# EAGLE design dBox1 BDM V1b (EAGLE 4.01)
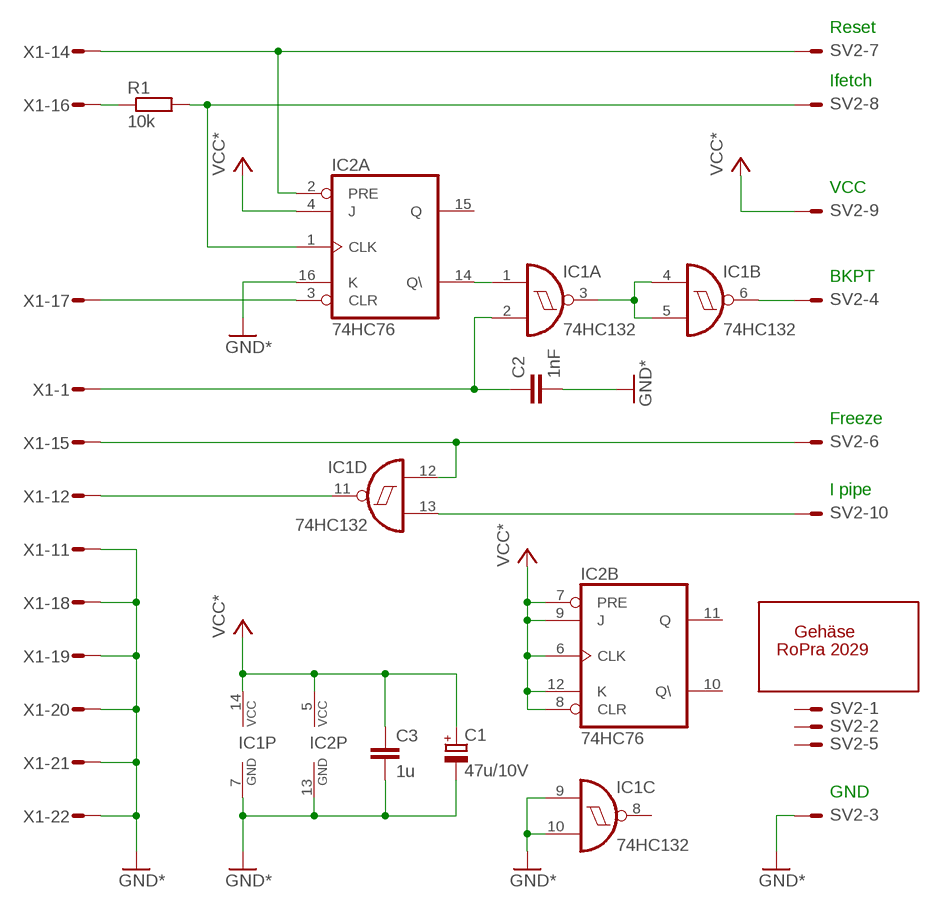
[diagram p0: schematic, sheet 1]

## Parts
C1  47u/10V  CPOL-EUE2.5-6  [E2,5-6]
C2  1nF  C-EU050-024X044  [C050-024X044]
C3  1u  C-EU050-024X044  [C050-024X044]
IC1  74HC132  74LS132N  [DIL14]
IC2  74HC76  7476N  [DIL16]
R1  10k  R-EU_0207/10  [0207/10]
SV2  ML10LE  [ML10L]
U$1  ROPRA2029A  [ROPRA2029]
X1  M25HS  [M25H]

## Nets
GND: C1.- C2.1 C3.1 IC1.7(P:GND) IC1.9(C:I0) IC1.10(C:I1) IC2.13(P:GND) IC2.16(A:K) SV2.3 X1.11 X1.18 X1.19 X1.20 X1.21 X1.22 ; supply symbol labelled GND*
N$1: IC1.11(D:O) X1.12
N$2: IC1.12(D:I0) SV2.6 X1.15
N$3: IC1.13(D:I1) SV2.10
N$4: IC1.1(A:I0) IC2.14(A:Q\)
N$5: IC2.2(A:PRE) SV2.7 X1.14
N$6: R1.1 X1.16
N$7: IC2.1(A:CLK) R1.2 SV2.8
N$9: IC1.3(A:O) IC1.4(B:I0) IC1.5(B:I1)
N$10: IC1.6(B:O) SV2.4
N$12: IC2.3(A:CLR) X1.17
N$13: C2.2 IC1.2(A:I1) X1.1
VCC: C1.+ C3.2 IC1.14(P:VCC) IC2.4(A:J) IC2.5(P:VCC) IC2.6(B:CLK) IC2.7(B:PRE) IC2.8(B:CLR) IC2.9(B:J) IC2.12(B:K) SV2.9 ; supply symbol labelled VCC*
Unconnected: IC1.8(C:O) IC2.10(B:Q\) IC2.11(B:Q) IC2.15(A:Q) SV2.1 SV2.2 SV2.5 X1.2 X1.3 X1.4 X1.5 X1.6 X1.7 X1.8 X1.9 X1.10 X1.13 X1.23 X1.24 X1.25

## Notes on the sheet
- Reset
- Ifetch
- VCC
- BKPT
- Freeze
- I pipe
- GND

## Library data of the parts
C1 = rcl:CPOL-EU: POLARIZED CAPACITOR, European symbol
C2 C3 = rcl:C-EU: CAPACITOR, European symbol
IC1 = 74xx-eu:74*132: Quad 2-input NAND schmitt trigger
IC2 = 74xx-eu:74*76: Dual J-K FLIP FLOP, preset and clear
R1 = rcl:R-EU_: RESISTOR, European symbol
SV2 = con-ml:ML10LE: HARTING
U$1 = 1st Helmut:ROPRA2029
X1 = con-subd:M25HS: HARTING SUB-D

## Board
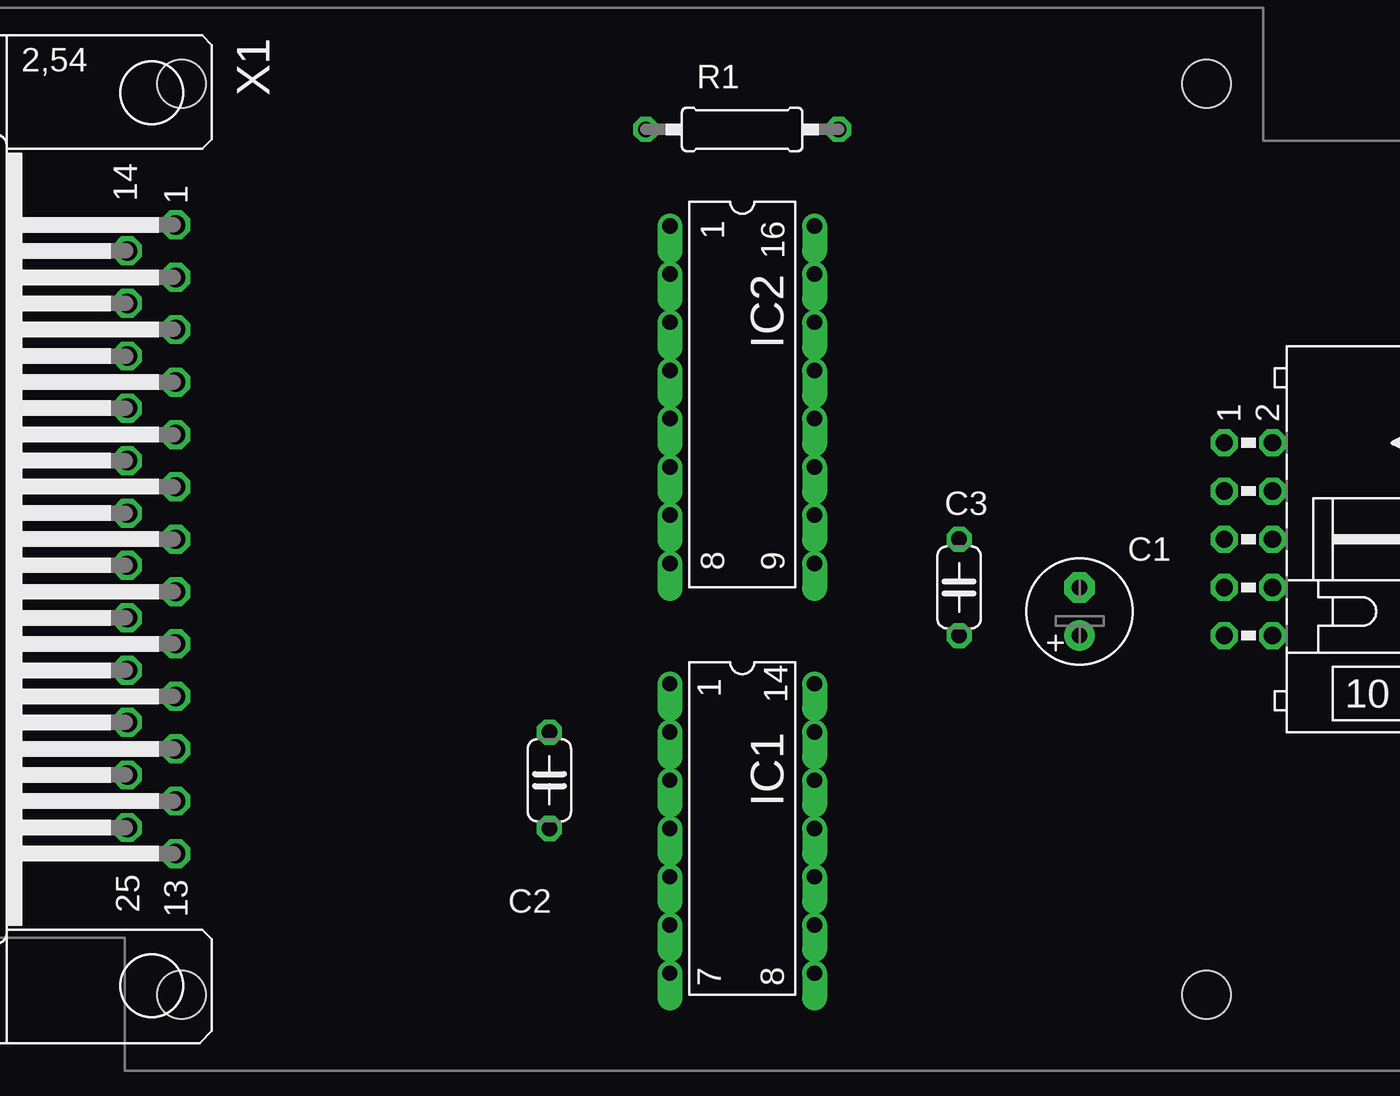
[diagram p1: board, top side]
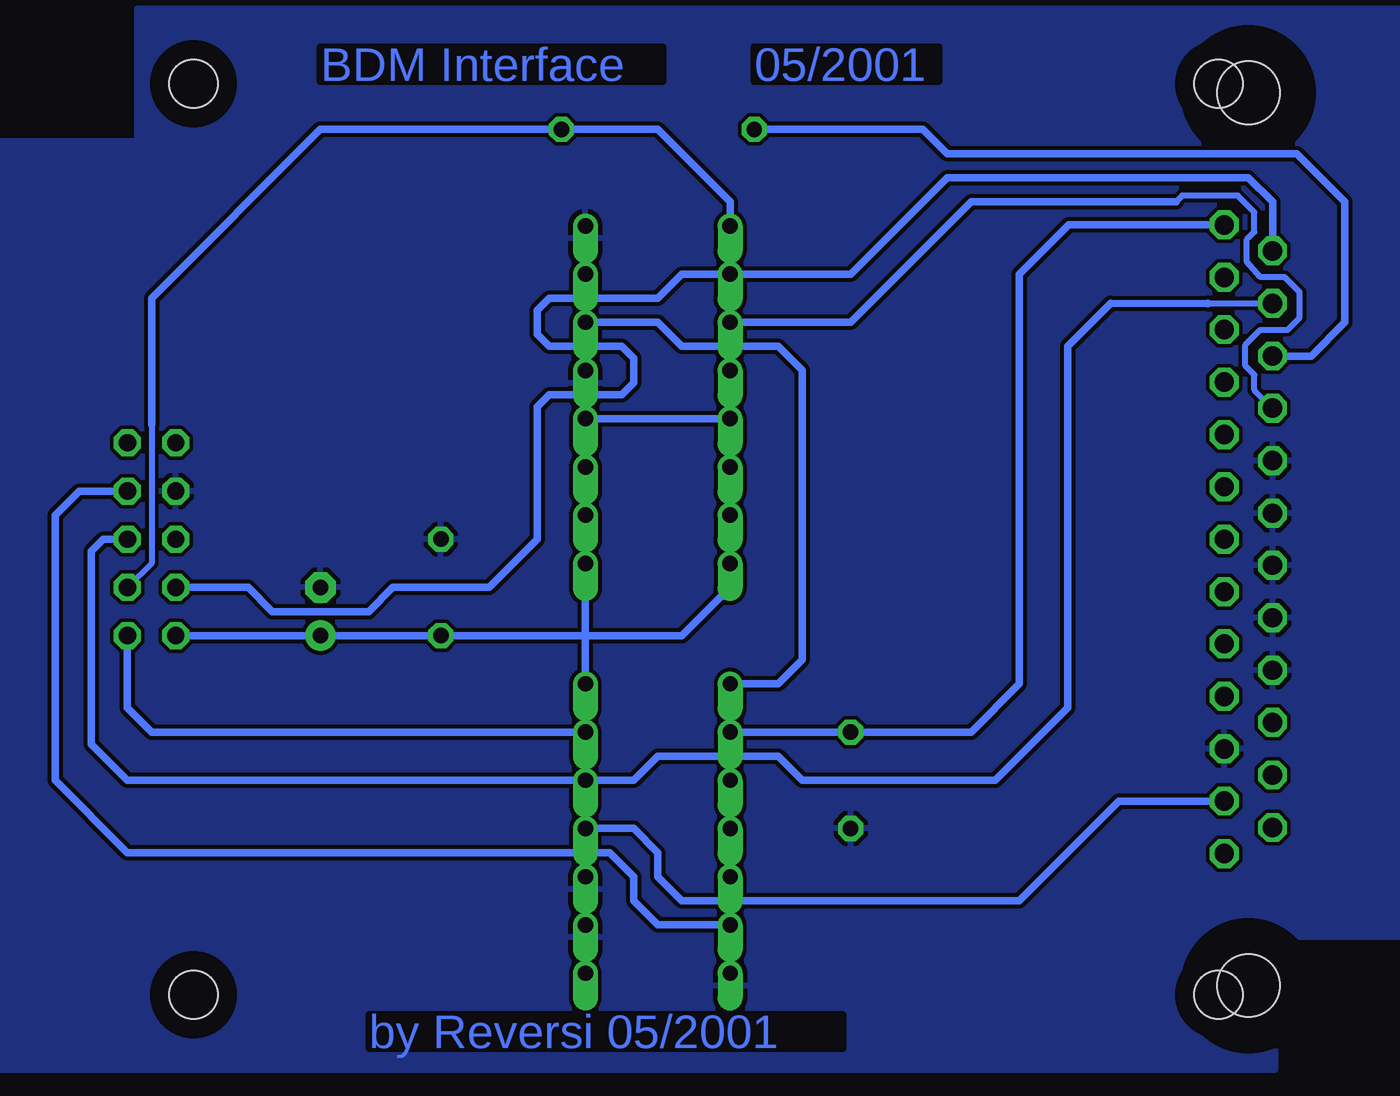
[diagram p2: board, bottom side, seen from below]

No outline drawn. Coordinates in mm, seen from the top.
Copper layers used: Bottom

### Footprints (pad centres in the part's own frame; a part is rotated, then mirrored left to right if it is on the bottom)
E2,5-6 = drill 0.813 pad 1.6 round: + -1.27,0 | drill 0.813 pad 1.6 octagon: - 1.27,0
C050-024X044 = drill 0.813 octagon: 1 -2.54,0; 2 2.54,0
DIL14 = drill 0.8 offset: 1 -7.62,-3.81; 2 -5.08,-3.81; 3 -2.54,-3.81; 4 0,-3.81; 5 2.54,-3.81; 6 5.08,-3.81; 7 7.62,-3.81; 8 7.62,3.81; 9 5.08,3.81; 10 2.54,3.81; 11 0,3.81; 12 -2.54,3.81; 13 -5.08,3.81; 14 -7.62,3.81
DIL16 = drill 0.813 offset: 1 -8.89,-3.81; 2 -6.35,-3.81; 3 -3.81,-3.81; 4 -1.27,-3.81; 5 1.27,-3.81; 6 3.81,-3.81; 7 6.35,-3.81; 8 8.89,-3.81; 9 8.89,3.81; 10 6.35,3.81; 11 3.81,3.81; 12 1.27,3.81; 13 -1.27,3.81; 14 -3.81,3.81; 15 -6.35,3.81; 16 -8.89,3.81
0207/10 = drill 0.813 octagon: 1 -5.08,0; 2 5.08,0
ML10L = drill 0.914 octagon: 1 -5.08,-1.27; 2 -5.08,1.27; 3 -2.54,-1.27; 4 -2.54,1.27; 5 0,-1.27; 6 0,1.27; 7 2.54,-1.27; 8 2.54,1.27; 9 5.08,-1.27; 10 5.08,1.27
ROPRA2029 = hole 2.54: -27,24; -27,-24; 27,-24; 27,24
M25H = drill 1.016 octagon: 1 -16.561,1.27; 2 -13.792,1.27; 3 -11.049,1.27; 4 -8.28,1.27; 5 -5.512,1.27; 6 -2.769,1.27; 7 0,1.27; 8 2.769,1.27; 9 5.512,1.27; 10 8.28,1.27; 11 11.049,1.27; 12 13.792,1.27; 13 16.561,1.27; 14 -15.189,-1.27; 15 -12.421,-1.27; 16 -9.652,-1.27; 17 -6.909,-1.27; 18 -4.14,-1.27; 19 -1.372,-1.27; 20 1.372,-1.27; 21 4.14,-1.27; 22 6.909,-1.27; 23 9.652,-1.27; 24 12.421,-1.27; 25 15.189,-1.27 | hole 3.302: 23.52,0; -23.52,0

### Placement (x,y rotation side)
C1  60.01,26.35 90 top
C2  32.07,17.46 90 top
C3  53.66,27.62 270 top
IC1  42.23,14.92 270 top
IC2  42.23,37.78 270 top
R1  42.23,51.75 0 top
SV2  68.9,30.16 270 top
U$1  39.69,30.16 0 top
X1  11.11,30.16 270 top

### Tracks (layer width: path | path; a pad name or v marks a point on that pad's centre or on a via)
GND
  pour Bottom: 2.22,58.1 69.69,58.1 69.69,51.12 77.15,51.12 77.15,2.22 9.68,2.22 9.68,9.21 2.22,9.21
N$1
  Bottom 0.406: IC1.11 43.5,14.92 42.23,13.65 42.23,12.38 40.96,11.11 23.18,11.11 17.94,16.35 12.38,16.35 X1.12
N$2
  Bottom 0.305: 13.26,42.58 X1.15
  Bottom 0.406: SV2.6 71.44,30.16 72.07,29.53 72.07,19.37 70.17,17.46 IC1.12 43.5,17.46 42.23,18.73 35.88,18.73 34.61,17.46 24.45,17.46 20.64,21.27 20.64,40.32 18.38,42.58 13.26,42.58
N$3
  Bottom 0.406: IC1.13 68.9,20 70.17,21.27 SV2.10
N$4
  Bottom 0.406: IC2.14 42.23,41.59 40.96,40.32 35.88,40.32 34.61,39.05 34.61,23.81 35.88,22.54 IC1.1
N$5
  Bottom 0.406: SV2.7 63.82,27.62 62.55,26.35 57.47,26.35 56.2,27.62 51.12,27.62 48.58,30.16 48.58,37.15 47.94,37.78 44.13,37.78 43.5,38.42 43.5,39.69 44.13,40.32 47.94,40.32 48.58,40.96 48.58,42.23 47.94,42.86 42.23,42.86 40.96,44.13 IC2.2 32.07,44.13 26.99,49.21 11.11,49.21 9.84,47.94 X1.14
N$6
  Bottom 0.406: R1.1 28.26,51.75 26.99,50.48 8.57,50.48 6.03,47.94 6.03,41.59 7.81,39.81 X1.16
N$7
  Bottom 0.305: 68.9,36.2 68.9,28.89 SV2.8
  Bottom 0.406: IC2.1 38.42,47.94 42.23,51.75 R1.2 60.01,51.75 68.9,42.86 68.9,36.2
N$9
  Bottom 0.406: IC1.3 IC1.4 IC1.5
N$10
  Bottom 0.406: IC1.6 42.23,9.84 43.5,11.11 43.5,12.38 44.77,13.65 70.17,13.65 73.98,17.46 73.98,31.43 72.71,32.7 SV2.4
N$12  (1 unrouted)
  Bottom 0.305: 8.97,41.28 8.41,41.83 8.41,43.18 9.21,43.98 10.48,43.98 11.19,44.77 11.19,45.96 10.79,46.36 10.79,47.39 11.67,48.26 14.6,48.26 14.92,47.94 | 8.97,41.28 | 8.97,41.28 9.05,41.2 10.48,41.2 11.27,40.4 11.27,39.29 10.79,38.81 10.79,38.02 X1.17
  Bottom 0.406: IC2.3 32.07,41.59 25.72,47.94 14.92,47.94
N$13
  Bottom 0.406: X1.1 20.59,46.72 23.18,44.13 23.18,22.54 25.72,20 C2.2 IC1.2
VCC
  Bottom 0.406: 46.04,25.08 C3.2 | C3.2 C1.+ | C1.+ SV2.9 C1.+ | 46.04,25.08 IC1.14 | IC2.5 IC2.4 | IC2.5 IC2.6 IC2.7 IC2.8 38.42,27.62 40.96,25.08 46.04,25.08 | C3.2 C1.+ | IC2.5 IC2.12 | 46.04,25.08 IC2.9

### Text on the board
Bottom: 05/2001 | BDM Interface | by Reversi 05/2001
